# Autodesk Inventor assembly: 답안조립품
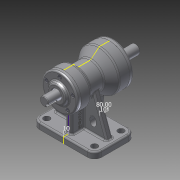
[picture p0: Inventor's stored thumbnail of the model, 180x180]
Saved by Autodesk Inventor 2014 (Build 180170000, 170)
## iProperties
Created: 2015-08
Part Number: 답안조립품
Document SubType Name: Assembly
Designer: Owner
Author: Owner
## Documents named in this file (10)
- C:\Documents and Settings\Owner\바탕 화면\450805V1004\답안조립품.iam
- C:\Documents and Settings\Owner\바탕 화면\450805V1004\본체.ipt
- C:\Documents and Settings\Owner\바탕 화면\450805V1004\축.ipt
- C:\Documents and Settings\Owner\바탕 화면\450805V1004\뒤커버.ipt
- C:\Documents and Settings\Owner\바탕 화면\450805V1004\앞커버.ipt
- C:\Documents and Settings\Owner\바탕 화면\450805V1004\오일실 .ipt
- 오일실 .ipt
- C:\Documents and Settings\Owner\바탕 화면\450805V1004\베어링 6205.ipt
- C:\Documents and Settings\Owner\바탕 화면\450805V1004\베어링 6203.ipt
- C:\Documents and Settings\Owner\바탕 화면\450805V1004\M4x0.5.ipt
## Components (10 placed, 1 different names)
1. M4x0.5:1
2. M4x0.5:3
3. M4x0.5:4
4. M4x0.5:5
5. M4x0.5:6
6. M4x0.5:2
7. M4x0.5:7
8. M4x0.5:8
9. M4x0.5:9
10. M4x0.5:10
